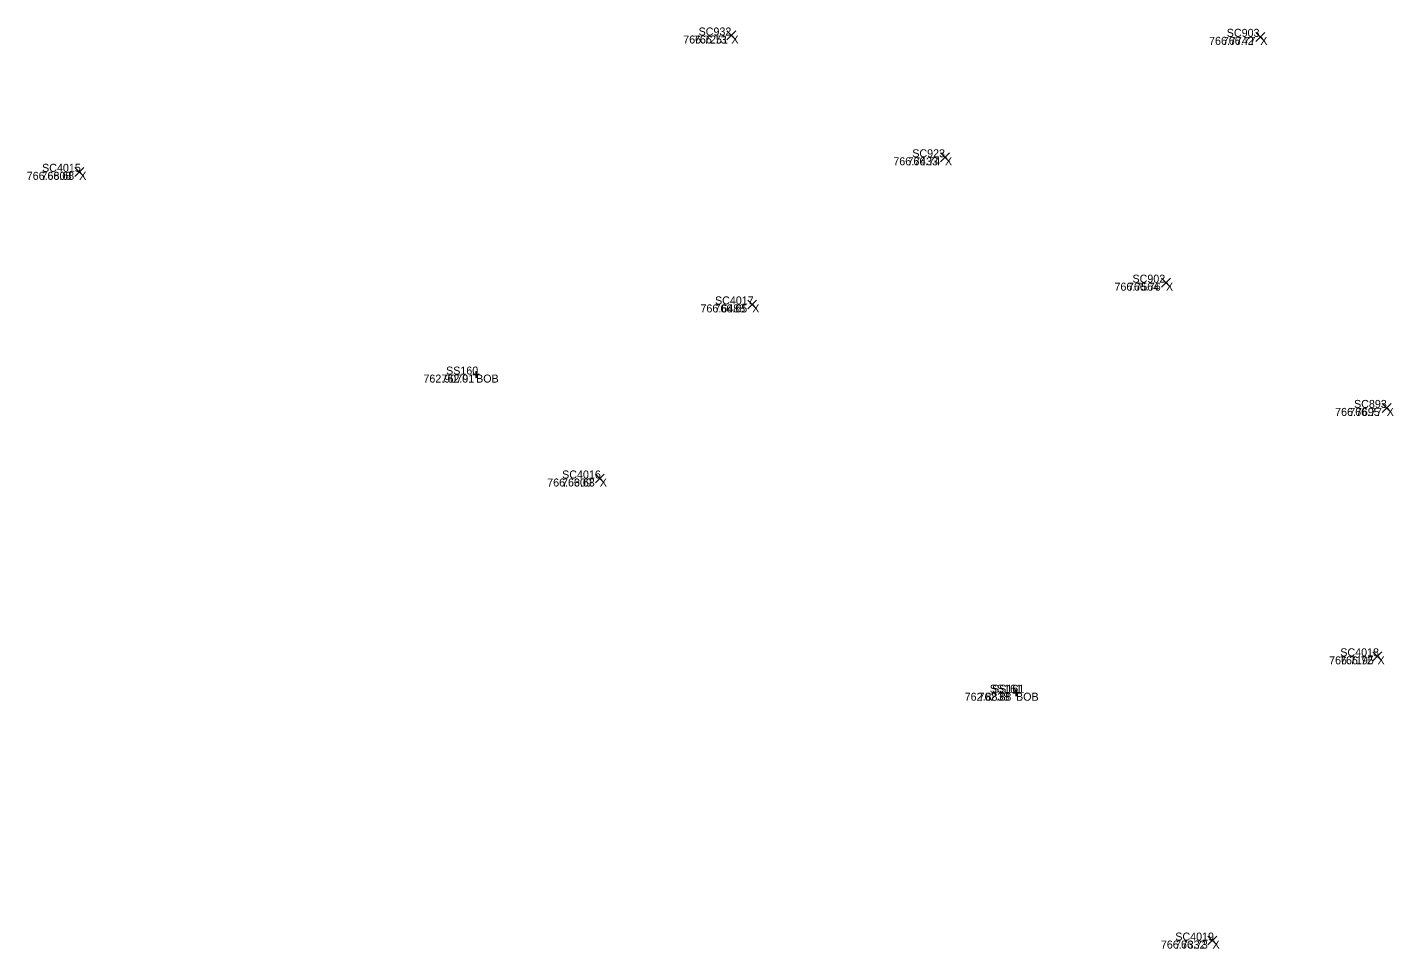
# Model space of a CAD drawing. Extents: x 1845019 to 1877956, y 680444 to 701081.
# Drawn here: x 1857582.16 to 1857592.4, y 694308.9 to 694315.81 of the extents above; entities that cross this region are included whole.
import ezdxf

# ---------------------------------------------------------------- set-up
doc = ezdxf.new("R2010")
doc.units = 0
for name, color, linetype in [('BR_X_SV_Bottom_of_Beam_Text', 7, 'Continuous'), ('SV_X_Random_Point', 7, 'Continuous'), ('SV_X_Text_Comment', 7, 'Continuous'), ('SV_X_Text_Elevation', 7, 'Continuous'), ('SV_X_Text_Name', 7, 'Continuous')]:
    doc.layers.add(name, color=color, linetype=linetype)

msp = doc.modelspace()

# ---------------------------------------------------------------- linework, layer by layer
at = {"layer": 'BR_X_SV_Bottom_of_Beam_Text'}
for p, q in [((1857585.523, 694313.231), (1857585.523, 694313.181)), ((1857585.523, 694313.231), (1857585.523, 694313.181)), ((1857585.498, 694313.206), (1857585.548, 694313.206)), ((1857585.498, 694313.206), (1857585.548, 694313.206)), ((1857585.523, 694313.206), (1857585.523, 694313.206)), ((1857585.523, 694313.206), (1857585.523, 694313.206)), ((1857589.546, 694310.821), (1857589.596, 694310.821)), ((1857589.546, 694310.821), (1857589.596, 694310.821)), ((1857589.571, 694310.846), (1857589.571, 694310.796)), ((1857589.571, 694310.846), (1857589.571, 694310.796)), ((1857589.571, 694310.821), (1857589.571, 694310.821)), ((1857589.571, 694310.821), (1857589.571, 694310.821))]:
    msp.add_line(p, q, dxfattribs=at)
at = {"layer": 'SV_X_Random_Point'}
for p, q in [((1857587.403, 694315.715), (1857587.47, 694315.782)), ((1857587.403, 694315.782), (1857587.47, 694315.715)), ((1857587.403, 694315.715), (1857587.47, 694315.782)), ((1857587.403, 694315.782), (1857587.47, 694315.715)), ((1857591.369, 694315.704), (1857591.435, 694315.771)), ((1857591.369, 694315.771), (1857591.435, 694315.704)), ((1857591.369, 694315.704), (1857591.435, 694315.771)), ((1857591.369, 694315.771), (1857591.435, 694315.704)), ((1857589.004, 694314.802), (1857589.071, 694314.869)), ((1857589.004, 694314.869), (1857589.071, 694314.802)), ((1857589.004, 694314.802), (1857589.071, 694314.869)), ((1857589.004, 694314.869), (1857589.071, 694314.802)), ((1857582.514, 694314.692), (1857582.581, 694314.759)), ((1857582.514, 694314.759), (1857582.581, 694314.692)), ((1857582.514, 694314.692), (1857582.581, 694314.759)), ((1857582.514, 694314.759), (1857582.581, 694314.692)), ((1857590.661, 694313.862), (1857590.728, 694313.928)), ((1857590.661, 694313.928), (1857590.728, 694313.862)), ((1857590.661, 694313.862), (1857590.728, 694313.928)), ((1857590.661, 694313.928), (1857590.728, 694313.862)), ((1857587.56, 694313.699), (1857587.626, 694313.765)), ((1857587.56, 694313.765), (1857587.626, 694313.699)), ((1857587.56, 694313.699), (1857587.626, 694313.765)), ((1857587.56, 694313.765), (1857587.626, 694313.699)), ((1857592.317, 694312.922), (1857592.384, 694312.989)), ((1857592.317, 694312.989), (1857592.384, 694312.922)), ((1857592.317, 694312.922), (1857592.384, 694312.989)), ((1857592.317, 694312.989), (1857592.384, 694312.922)), ((1857586.417, 694312.394), (1857586.483, 694312.46)), ((1857586.417, 694312.46), (1857586.483, 694312.394)), ((1857586.417, 694312.394), (1857586.483, 694312.46)), ((1857586.417, 694312.46), (1857586.483, 694312.394)), ((1857592.247, 694311.06), (1857592.314, 694311.127)), ((1857592.247, 694311.127), (1857592.314, 694311.06)), ((1857592.247, 694311.06), (1857592.314, 694311.127)), ((1857592.247, 694311.127), (1857592.314, 694311.06)), ((1857591.01, 694308.93), (1857591.077, 694308.996)), ((1857591.01, 694308.996), (1857591.077, 694308.93)), ((1857591.01, 694308.93), (1857591.077, 694308.996)), ((1857591.01, 694308.996), (1857591.077, 694308.93))]:
    msp.add_line(p, q, dxfattribs=at)

# ---------------------------------------------------------------- texts
at = {"layer": 'BR_X_SV_Bottom_of_Beam_Text'}
for s, p in [('SS160', (1857585.298, 694313.206)), ('SS160', (1857585.298, 694313.206)), ('762.9070', (1857585.128, 694313.146)), ('762.91', (1857585.264, 694313.146)), ('BOB', (1857585.523, 694313.146)), ('SS161', (1857589.374, 694310.821)), ('SS161', (1857589.391, 694310.821)), ('762.8838', (1857589.186, 694310.761)), ('762.88', (1857589.29, 694310.761)), ('BOB', (1857589.571, 694310.761))]:
    msp.add_text(s, height=0.06, dxfattribs=at).set_placement(p)
at = {"layer": 'SV_X_Text_Comment'}
for p in [(1857587.437, 694315.688), (1857591.402, 694315.678), (1857589.038, 694314.775), (1857582.547, 694314.666), (1857590.695, 694313.835), (1857587.593, 694313.672), (1857592.35, 694312.896), (1857586.45, 694312.367), (1857592.281, 694311.034), (1857591.044, 694308.903)]:
    msp.add_text('X', height=0.06, dxfattribs=at).set_placement(p)
at = {"layer": 'SV_X_Text_Elevation'}
for s, p in [('766.7251', (1857587.076, 694315.688)), ('766.73', (1857587.156, 694315.688)), ('766.7742', (1857591.018, 694315.678)), ('766.77', (1857591.121, 694315.678)), ('766.7433', (1857588.651, 694314.775)), ('766.74', (1857588.757, 694314.775)), ('766.6808', (1857582.154, 694314.666)), ('766.68', (1857582.264, 694314.666)), ('766.7564', (1857590.309, 694313.835)), ('766.76', (1857590.41, 694313.835)), ('766.6488', (1857587.205, 694313.672)), ('766.65', (1857587.31, 694313.672)), ('766.7695', (1857591.963, 694312.896)), ('766.77', (1857592.069, 694312.896)), ('766.6309', (1857586.056, 694312.367)), ('766.63', (1857586.167, 694312.367)), ('766.7195', (1857591.918, 694311.034)), ('766.72', (1857592, 694311.034)), ('766.7332', (1857590.657, 694308.903)), ('766.73', (1857590.763, 694308.903))]:
    msp.add_text(s, height=0.06, dxfattribs=at).set_placement(p)
at = {"layer": 'SV_X_Text_Name'}
for s, p in [('SC932', (1857587.191, 694315.748)), ('SC932', (1857587.191, 694315.748)), ('SC903', (1857591.151, 694315.738)), ('SC903', (1857591.151, 694315.738)), ('SC923', (1857588.793, 694314.835)), ('SC923', (1857588.793, 694314.835)), ('SC4015', (1857582.269, 694314.726)), ('SC4015', (1857582.269, 694314.726)), ('SC902', (1857590.444, 694313.895)), ('SC902', (1857590.444, 694313.895)), ('SC4017', (1857587.314, 694313.732)), ('SC4017', (1857587.314, 694313.732)), ('SC893', (1857592.105, 694312.956)), ('SC893', (1857592.105, 694312.956)), ('SC4016', (1857586.168, 694312.427)), ('SC4016', (1857586.168, 694312.427)), ('SC4018', (1857592.002, 694311.094)), ('SC4018', (1857592.002, 694311.094)), ('SC4019', (1857590.765, 694308.963)), ('SC4019', (1857590.765, 694308.963))]:
    msp.add_text(s, height=0.06, dxfattribs=at).set_placement(p)

doc.saveas('drawing.dxf')
